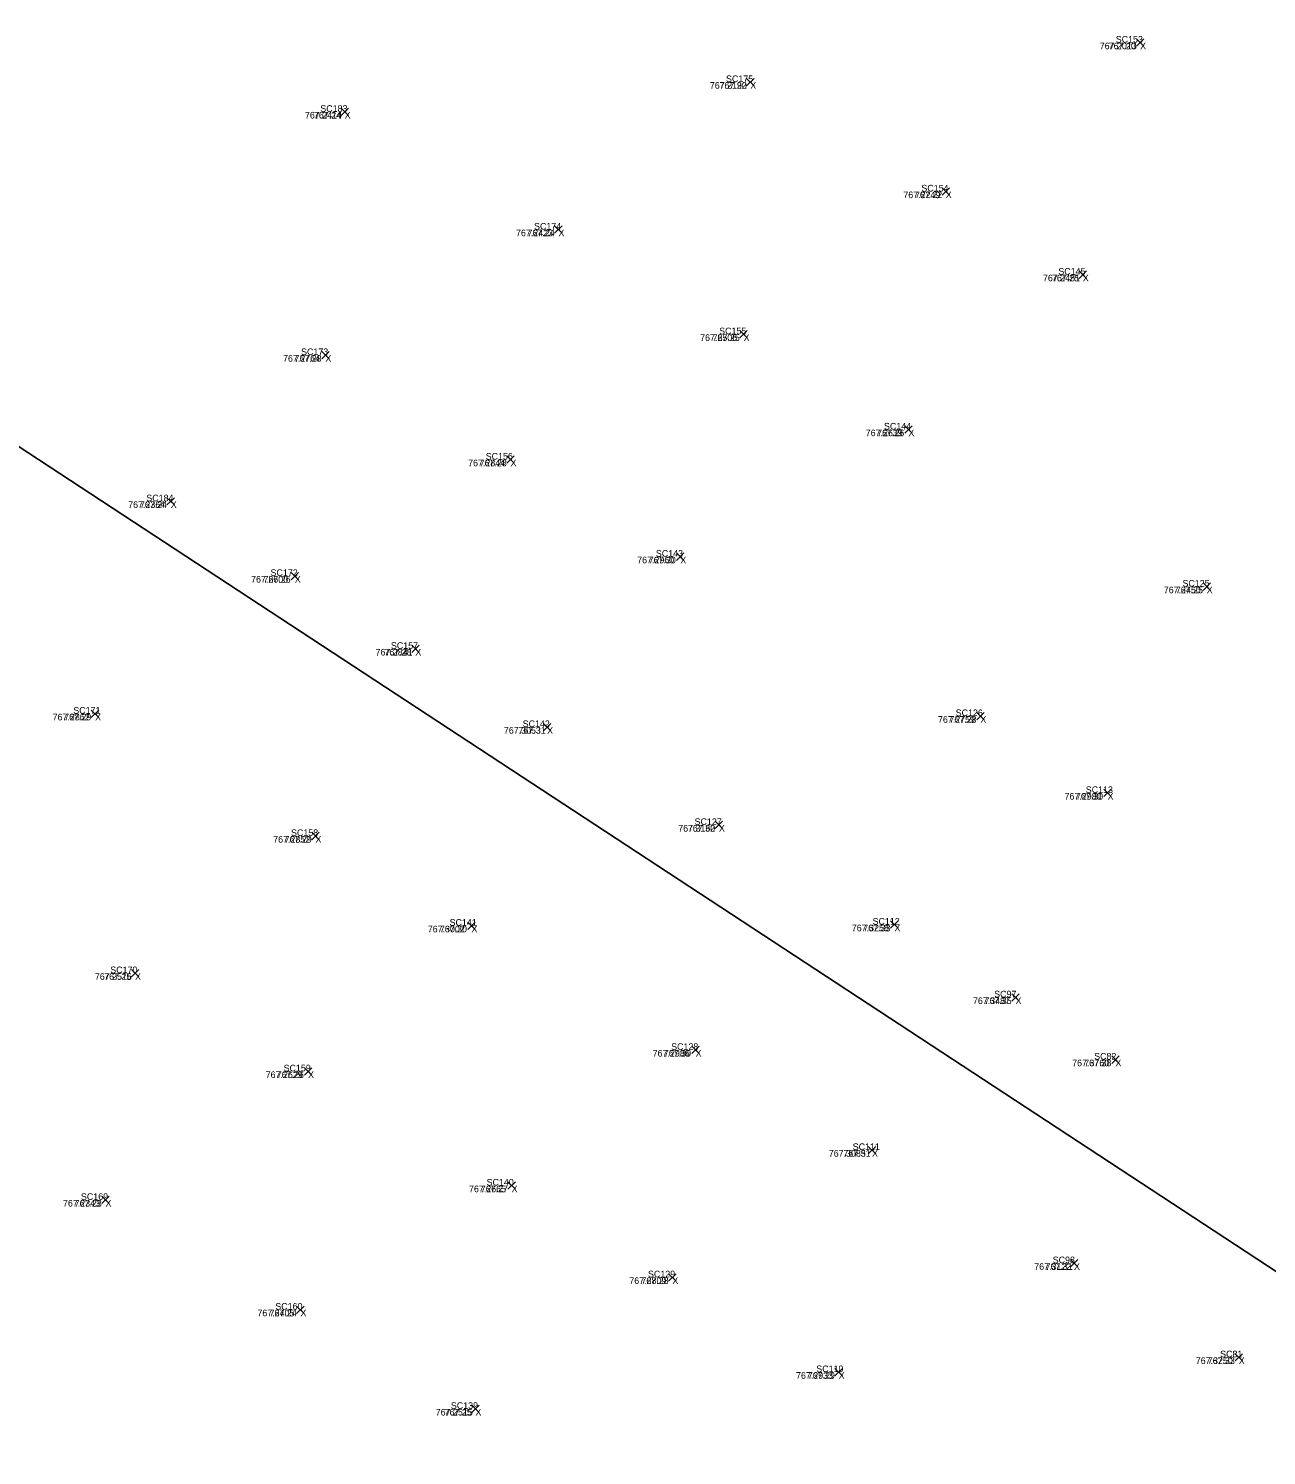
# Model space of a CAD drawing. Extents: x 1845019 to 1877956, y 680444 to 701081.
# Drawn here: x 1857673.54 to 1857684.73, y 694264.34 to 694277.24 of the extents above; entities that cross this region are included whole.
import ezdxf

# ---------------------------------------------------------------- set-up
doc = ezdxf.new("R2010")
doc.units = 0
for name, color, linetype in [('SV_X_CL_Survey_20', 7, 'Continuous'), ('SV_X_Random_Point', 7, 'Continuous'), ('SV_X_Text_Comment', 7, 'Continuous'), ('SV_X_Text_Elevation', 7, 'Continuous'), ('SV_X_Text_Name', 7, 'Continuous')]:
    doc.layers.add(name, color=color, linetype=linetype)

msp = doc.modelspace()

# ---------------------------------------------------------------- linework, layer by layer
at = {"layer": 'SV_X_CL_Survey_20'}
msp.add_line((1856038.267, 695346.314), (1858797.327, 693536.085), dxfattribs=at)
at = {"layer": 'SV_X_Random_Point'}
for p, q in [((1857683.555, 694277.084), (1857683.622, 694277.151)), ((1857683.555, 694277.151), (1857683.622, 694277.084)), ((1857683.555, 694277.084), (1857683.622, 694277.151)), ((1857683.555, 694277.151), (1857683.622, 694277.084)), ((1857680.031, 694276.727), (1857680.098, 694276.793)), ((1857680.031, 694276.793), (1857680.098, 694276.727)), ((1857680.031, 694276.727), (1857680.098, 694276.793)), ((1857680.031, 694276.793), (1857680.098, 694276.727)), ((1857676.365, 694276.458), (1857676.432, 694276.524)), ((1857676.365, 694276.524), (1857676.432, 694276.458)), ((1857676.365, 694276.458), (1857676.432, 694276.524)), ((1857676.365, 694276.524), (1857676.432, 694276.458)), ((1857681.798, 694275.738), (1857681.865, 694275.805)), ((1857681.798, 694275.805), (1857681.865, 694275.738)), ((1857681.798, 694275.738), (1857681.865, 694275.805)), ((1857681.798, 694275.805), (1857681.865, 694275.738)), ((1857678.296, 694275.393), (1857678.363, 694275.46)), ((1857678.296, 694275.46), (1857678.363, 694275.393)), ((1857678.296, 694275.393), (1857678.363, 694275.46)), ((1857678.296, 694275.46), (1857678.363, 694275.393)), ((1857683.036, 694274.986), (1857683.103, 694275.053)), ((1857683.036, 694275.053), (1857683.103, 694274.986)), ((1857683.036, 694274.986), (1857683.103, 694275.053)), ((1857683.036, 694275.053), (1857683.103, 694274.986)), ((1857679.97, 694274.447), (1857680.037, 694274.514)), ((1857679.97, 694274.514), (1857680.037, 694274.447)), ((1857679.97, 694274.447), (1857680.037, 694274.514)), ((1857679.97, 694274.514), (1857680.037, 694274.447)), ((1857676.191, 694274.259), (1857676.257, 694274.325)), ((1857676.191, 694274.325), (1857676.257, 694274.259)), ((1857676.191, 694274.259), (1857676.257, 694274.325)), ((1857676.191, 694274.325), (1857676.257, 694274.259)), ((1857681.46, 694273.586), (1857681.527, 694273.653)), ((1857681.46, 694273.653), (1857681.527, 694273.586)), ((1857681.46, 694273.586), (1857681.527, 694273.653)), ((1857681.46, 694273.653), (1857681.527, 694273.586)), ((1857677.864, 694273.314), (1857677.931, 694273.381)), ((1857677.864, 694273.381), (1857677.931, 694273.314)), ((1857677.864, 694273.314), (1857677.931, 694273.381)), ((1857677.864, 694273.381), (1857677.931, 694273.314)), ((1857674.792, 694272.937), (1857674.859, 694273.003)), ((1857674.792, 694273.003), (1857674.859, 694272.937)), ((1857674.792, 694272.937), (1857674.859, 694273.003)), ((1857674.792, 694273.003), (1857674.859, 694272.937)), ((1857679.398, 694272.436), (1857679.465, 694272.503)), ((1857679.398, 694272.503), (1857679.465, 694272.436)), ((1857679.398, 694272.436), (1857679.465, 694272.503)), ((1857679.398, 694272.503), (1857679.465, 694272.436)), ((1857675.914, 694272.261), (1857675.981, 694272.328)), ((1857675.914, 694272.328), (1857675.981, 694272.261)), ((1857675.914, 694272.261), (1857675.981, 694272.328)), ((1857675.914, 694272.328), (1857675.981, 694272.261)), ((1857684.157, 694272.165), (1857684.224, 694272.232)), ((1857684.157, 694272.232), (1857684.224, 694272.165)), ((1857684.157, 694272.165), (1857684.224, 694272.232)), ((1857684.157, 694272.232), (1857684.224, 694272.165)), ((1857677.004, 694271.603), (1857677.07, 694271.67)), ((1857677.004, 694271.67), (1857677.07, 694271.603)), ((1857677.004, 694271.603), (1857677.07, 694271.67)), ((1857677.004, 694271.67), (1857677.07, 694271.603)), ((1857674.108, 694271.017), (1857674.175, 694271.083)), ((1857674.108, 694271.083), (1857674.175, 694271.017)), ((1857674.108, 694271.017), (1857674.175, 694271.083)), ((1857674.108, 694271.083), (1857674.175, 694271.017)), ((1857682.111, 694270.994), (1857682.177, 694271.061)), ((1857682.111, 694271.061), (1857682.177, 694270.994)), ((1857682.111, 694270.994), (1857682.177, 694271.061)), ((1857682.111, 694271.061), (1857682.177, 694270.994)), ((1857678.195, 694270.896), (1857678.261, 694270.962)), ((1857678.195, 694270.962), (1857678.261, 694270.896)), ((1857678.195, 694270.896), (1857678.261, 694270.962)), ((1857678.195, 694270.962), (1857678.261, 694270.896)), ((1857683.261, 694270.3), (1857683.327, 694270.367)), ((1857683.261, 694270.367), (1857683.327, 694270.3)), ((1857683.261, 694270.3), (1857683.327, 694270.367)), ((1857683.261, 694270.367), (1857683.327, 694270.3)), ((1857676.101, 694269.911), (1857676.168, 694269.978)), ((1857676.101, 694269.978), (1857676.168, 694269.911)), ((1857676.101, 694269.911), (1857676.168, 694269.978)), ((1857676.101, 694269.978), (1857676.168, 694269.911)), ((1857679.747, 694270.011), (1857679.814, 694270.077)), ((1857679.747, 694270.077), (1857679.814, 694270.011)), ((1857679.747, 694270.011), (1857679.814, 694270.077)), ((1857679.747, 694270.077), (1857679.814, 694270.011)), ((1857677.511, 694269.099), (1857677.578, 694269.166)), ((1857677.511, 694269.166), (1857677.578, 694269.099)), ((1857677.511, 694269.099), (1857677.578, 694269.166)), ((1857677.511, 694269.166), (1857677.578, 694269.099)), ((1857681.333, 694269.11), (1857681.4, 694269.176)), ((1857681.333, 694269.176), (1857681.4, 694269.11)), ((1857681.333, 694269.11), (1857681.4, 694269.176)), ((1857681.333, 694269.176), (1857681.4, 694269.11)), ((1857674.47, 694268.67), (1857674.537, 694268.737)), ((1857674.47, 694268.737), (1857674.537, 694268.67)), ((1857674.47, 694268.67), (1857674.537, 694268.737)), ((1857674.47, 694268.737), (1857674.537, 694268.67)), ((1857682.429, 694268.451), (1857682.495, 694268.518)), ((1857682.429, 694268.518), (1857682.495, 694268.451)), ((1857682.429, 694268.451), (1857682.495, 694268.518)), ((1857682.429, 694268.518), (1857682.495, 694268.451)), ((1857679.536, 694267.977), (1857679.603, 694268.043)), ((1857679.536, 694268.043), (1857679.603, 694267.977)), ((1857679.536, 694267.977), (1857679.603, 694268.043)), ((1857679.536, 694268.043), (1857679.603, 694267.977)), ((1857683.331, 694267.889), (1857683.398, 694267.956)), ((1857683.331, 694267.956), (1857683.398, 694267.889)), ((1857683.331, 694267.889), (1857683.398, 694267.956)), ((1857683.331, 694267.956), (1857683.398, 694267.889)), ((1857676.034, 694267.782), (1857676.1, 694267.849)), ((1857676.034, 694267.849), (1857676.1, 694267.782)), ((1857676.034, 694267.782), (1857676.1, 694267.849)), ((1857676.034, 694267.849), (1857676.1, 694267.782)), ((1857681.131, 694267.072), (1857681.198, 694267.138)), ((1857681.131, 694267.138), (1857681.198, 694267.072)), ((1857681.131, 694267.072), (1857681.198, 694267.138)), ((1857681.131, 694267.138), (1857681.198, 694267.072)), ((1857677.874, 694266.75), (1857677.941, 694266.817)), ((1857677.874, 694266.817), (1857677.941, 694266.75)), ((1857677.874, 694266.75), (1857677.941, 694266.817)), ((1857677.874, 694266.817), (1857677.941, 694266.75)), ((1857674.203, 694266.621), (1857674.27, 694266.688)), ((1857674.203, 694266.688), (1857674.27, 694266.621)), ((1857674.203, 694266.621), (1857674.27, 694266.688)), ((1857674.203, 694266.688), (1857674.27, 694266.621)), ((1857682.958, 694266.049), (1857683.025, 694266.116)), ((1857682.958, 694266.116), (1857683.025, 694266.049)), ((1857682.958, 694266.049), (1857683.025, 694266.116)), ((1857682.958, 694266.116), (1857683.025, 694266.049)), ((1857679.326, 694265.92), (1857679.393, 694265.987)), ((1857679.326, 694265.987), (1857679.393, 694265.92)), ((1857679.326, 694265.92), (1857679.393, 694265.987)), ((1857679.326, 694265.987), (1857679.393, 694265.92)), ((1857675.964, 694265.628), (1857676.031, 694265.695)), ((1857675.964, 694265.695), (1857676.031, 694265.628)), ((1857675.964, 694265.628), (1857676.031, 694265.695)), ((1857675.964, 694265.695), (1857676.031, 694265.628)), ((1857684.447, 694265.198), (1857684.514, 694265.264)), ((1857684.447, 694265.264), (1857684.514, 694265.198)), ((1857684.447, 694265.198), (1857684.514, 694265.264)), ((1857684.447, 694265.264), (1857684.514, 694265.198)), ((1857680.83, 694265.064), (1857680.897, 694265.13)), ((1857680.83, 694265.13), (1857680.897, 694265.064)), ((1857680.83, 694265.064), (1857680.897, 694265.13)), ((1857680.83, 694265.13), (1857680.897, 694265.064)), ((1857677.547, 694264.732), (1857677.614, 694264.798)), ((1857677.547, 694264.798), (1857677.614, 694264.732)), ((1857677.547, 694264.732), (1857677.614, 694264.798)), ((1857677.547, 694264.798), (1857677.614, 694264.732))]:
    msp.add_line(p, q, dxfattribs=at)

# ---------------------------------------------------------------- texts
at = {"layer": 'SV_X_Text_Comment'}
for p in [(1857683.588, 694277.057), (1857680.064, 694276.7), (1857676.398, 694276.431), (1857681.831, 694275.711), (1857678.33, 694275.367), (1857683.07, 694274.959), (1857680.004, 694274.42), (1857676.224, 694274.232), (1857681.494, 694273.559), (1857677.897, 694273.287), (1857674.826, 694272.91), (1857679.432, 694272.409), (1857675.947, 694272.235), (1857684.19, 694272.139), (1857677.037, 694271.576), (1857674.142, 694270.99), (1857682.144, 694270.968), (1857678.228, 694270.869), (1857683.294, 694270.273), (1857679.781, 694269.984), (1857676.134, 694269.884), (1857677.544, 694269.073), (1857681.367, 694269.083), (1857674.503, 694268.644), (1857682.462, 694268.425), (1857679.57, 694267.95), (1857683.365, 694267.863), (1857676.067, 694267.756), (1857681.165, 694267.045), (1857677.907, 694266.724), (1857674.236, 694266.594), (1857682.991, 694266.022), (1857679.36, 694265.894), (1857675.998, 694265.602), (1857684.48, 694265.171), (1857680.863, 694265.037), (1857677.58, 694264.705)]:
    msp.add_text('X', height=0.06, dxfattribs=at).set_placement(p)
at = {"layer": 'SV_X_Text_Elevation'}
for s, p in [('767.2013', (1857683.223, 694277.057)), ('767.20', (1857683.304, 694277.057)), ('767.2190', (1857679.699, 694276.7)), ('767.22', (1857679.786, 694276.7)), ('767.2414', (1857676.039, 694276.431)), ('767.24', (1857676.12, 694276.431)), ('767.2249', (1857681.448, 694275.711)), ('767.22', (1857681.553, 694275.711)), ('767.2423', (1857677.947, 694275.367)), ('767.24', (1857678.051, 694275.367)), ('767.2451', (1857682.71, 694274.959)), ('767.25', (1857682.791, 694274.959)), ('767.2506', (1857679.611, 694274.42)), ('767.25', (1857679.724, 694274.42)), ('767.2764', (1857675.841, 694274.232)), ('767.28', (1857675.944, 694274.232)), ('767.2639', (1857681.108, 694273.559)), ('767.26', (1857681.211, 694273.559)), ('767.2844', (1857677.514, 694273.287)), ('767.28', (1857677.618, 694273.287)), ('767.2364', (1857674.441, 694272.91)), ('767.24', (1857674.547, 694272.91)), ('767.2960', (1857679.042, 694272.409)), ('767.30', (1857679.146, 694272.409)), ('767.2600', (1857675.552, 694272.235)), ('767.26', (1857675.664, 694272.235)), ('767.2450', (1857683.802, 694272.139)), ('767.25', (1857683.911, 694272.139)), ('767.2841', (1857676.677, 694271.576)), ('767.28', (1857676.757, 694271.576)), ('767.2862', (1857673.758, 694270.99)), ('767.29', (1857673.862, 694270.99)), ('767.2759', (1857681.761, 694270.968)), ('767.28', (1857681.864, 694270.968)), ('767.3053', (1857677.837, 694270.869)), ('767.31', (1857677.969, 694270.869)), ('767.2980', (1857682.905, 694270.273)), ('767.30', (1857683.008, 694270.273)), ('767.3160', (1857679.413, 694269.984)), ('767.32', (1857679.5, 694269.984)), ('767.2852', (1857675.752, 694269.884)), ('767.29', (1857675.855, 694269.884)), ('767.3002', (1857677.149, 694269.073)), ('767.30', (1857677.258, 694269.073)), ('767.3258', (1857680.982, 694269.083)), ('767.33', (1857681.086, 694269.083)), ('767.2516', (1857674.14, 694268.644)), ('767.25', (1857674.224, 694268.644)), ('767.3487', (1857682.077, 694268.425)), ('767.35', (1857682.181, 694268.425)), ('767.2986', (1857679.182, 694267.95)), ('767.30', (1857679.283, 694267.95)), ('767.3760', (1857682.974, 694267.863)), ('767.38', (1857683.083, 694267.863)), ('767.2629', (1857675.684, 694267.756)), ('767.26', (1857675.784, 694267.756)), ('767.3085', (1857680.774, 694267.045)), ('767.31', (1857680.906, 694267.045)), ('767.2665', (1857677.522, 694266.724)), ('767.27', (1857677.628, 694266.724)), ('767.2343', (1857673.852, 694266.594)), ('767.23', (1857673.957, 694266.594)), ('767.3122', (1857682.631, 694266.022)), ('767.31', (1857682.733, 694266.022)), ('767.2809', (1857678.971, 694265.894)), ('767.28', (1857679.08, 694265.894)), ('767.2405', (1857675.609, 694265.602)), ('767.24', (1857675.719, 694265.602)), ('767.3250', (1857684.091, 694265.171)), ('767.33', (1857684.199, 694265.171)), ('767.2933', (1857680.478, 694265.037)), ('767.29', (1857680.584, 694265.037)), ('767.2515', (1857677.221, 694264.705)), ('767.25', (1857677.301, 694264.705))]:
    msp.add_text(s, height=0.06, dxfattribs=at).set_placement(p)
at = {"layer": 'SV_X_Text_Name'}
for s, p in [('SC153', (1857683.368, 694277.117)), ('SC153', (1857683.368, 694277.117)), ('SC175', (1857679.845, 694276.76)), ('SC175', (1857679.845, 694276.76)), ('SC183', (1857676.178, 694276.491)), ('SC183', (1857676.178, 694276.491)), ('SC154', (1857681.611, 694275.771)), ('SC154', (1857681.611, 694275.771)), ('SC174', (1857678.11, 694275.427)), ('SC174', (1857678.11, 694275.427)), ('SC145', (1857682.849, 694275.019)), ('SC145', (1857682.849, 694275.019)), ('SC155', (1857679.783, 694274.48)), ('SC155', (1857679.783, 694274.48)), ('SC173', (1857676.004, 694274.292)), ('SC173', (1857676.004, 694274.292)), ('SC144', (1857681.273, 694273.619)), ('SC144', (1857681.273, 694273.619)), ('SC156', (1857677.673, 694273.347)), ('SC156', (1857677.673, 694273.347)), ('SC184', (1857674.605, 694272.97)), ('SC184', (1857674.605, 694272.97)), ('SC143', (1857679.211, 694272.469)), ('SC143', (1857679.211, 694272.469)), ('SC172', (1857675.728, 694272.295)), ('SC172', (1857675.728, 694272.295)), ('SC125', (1857683.971, 694272.199)), ('SC125', (1857683.971, 694272.199)), ('SC157', (1857676.816, 694271.636)), ('SC157', (1857676.816, 694271.636)), ('SC171', (1857673.945, 694271.05)), ('SC171', (1857673.945, 694271.05)), ('SC126', (1857681.921, 694271.028)), ('SC126', (1857681.921, 694271.028)), ('SC142', (1857678.007, 694270.929)), ('SC142', (1857678.007, 694270.929)), ('SC113', (1857683.097, 694270.333)), ('SC113', (1857683.097, 694270.333)), ('SC127', (1857679.561, 694270.044)), ('SC127', (1857679.561, 694270.044)), ('SC158', (1857675.913, 694269.944)), ('SC158', (1857675.913, 694269.944)), ('SC112', (1857681.17, 694269.143)), ('SC112', (1857681.17, 694269.143)), ('SC141', (1857677.347, 694269.133)), ('SC141', (1857677.346, 694269.133)), ('SC170', (1857674.279, 694268.704)), ('SC170', (1857674.279, 694268.704)), ('SC97', (1857682.269, 694268.485)), ('SC97', (1857682.269, 694268.485)), ('SC128', (1857679.349, 694268.01)), ('SC128', (1857679.349, 694268.01)), ('SC82', (1857683.173, 694267.923)), ('SC82', (1857683.173, 694267.923)), ('SC159', (1857675.846, 694267.816)), ('SC159', (1857675.846, 694267.816)), ('SC111', (1857680.99, 694267.105)), ('SC111', (1857680.991, 694267.105)), ('SC140', (1857677.681, 694266.784)), ('SC140', (1857677.681, 694266.784)), ('SC169', (1857674.014, 694266.654)), ('SC169', (1857674.014, 694266.654)), ('SC98', (1857682.798, 694266.082)), ('SC98', (1857682.798, 694266.082)), ('SC129', (1857679.14, 694265.954)), ('SC129', (1857679.14, 694265.954)), ('SC160', (1857675.771, 694265.662)), ('SC160', (1857675.771, 694265.662)), ('SC81', (1857684.311, 694265.231)), ('SC81', (1857684.312, 694265.231)), ('SC110', (1857680.661, 694265.097)), ('SC110', (1857680.661, 694265.097)), ('SC139', (1857677.358, 694264.765)), ('SC139', (1857677.358, 694264.765))]:
    msp.add_text(s, height=0.06, dxfattribs=at).set_placement(p)

doc.saveas('drawing.dxf')
